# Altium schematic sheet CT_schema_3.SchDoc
size 372 x 328 mm
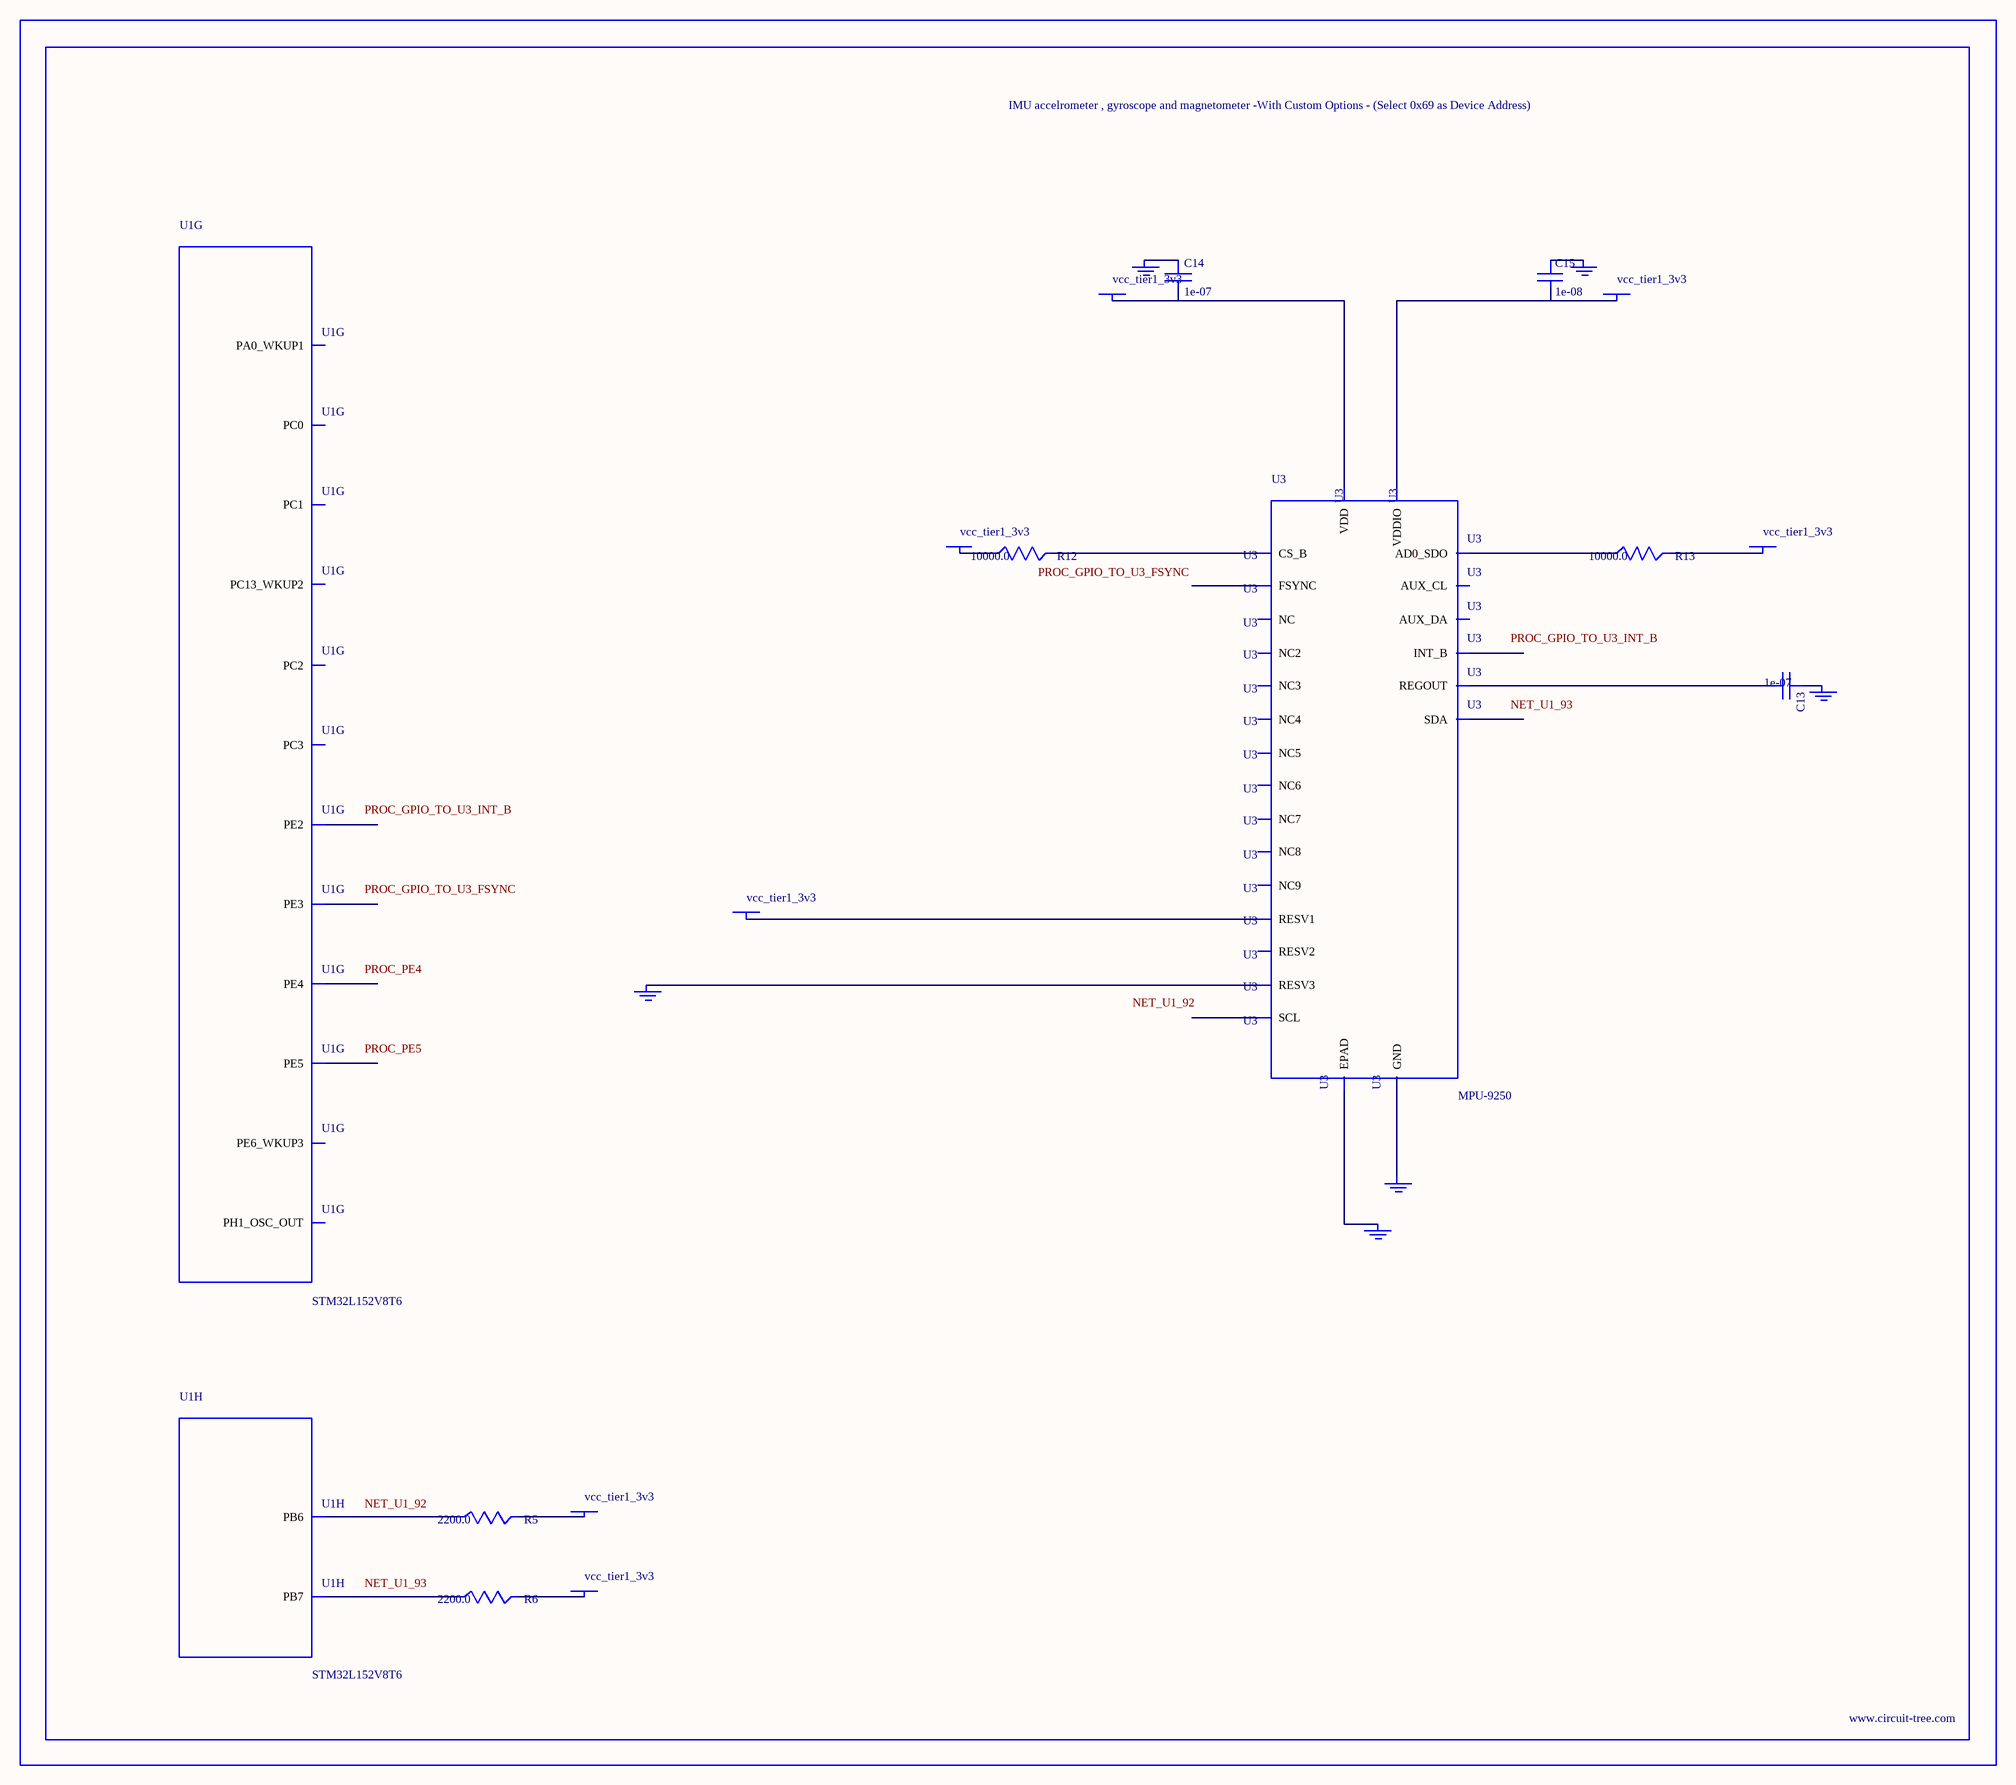
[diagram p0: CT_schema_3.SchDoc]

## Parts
BORDER2  (no value)
C13  1e-07  [C0402]
C14  1e-07  [C0402]
C15  1e-08  [C0402]
GND_INSTANCE_2_0  (no value)
GND_INSTANCE_2_1  (no value)
GND_INSTANCE_2_2  (no value)
GND_INSTANCE_2_3  (no value)
GND_INSTANCE_2_4  (no value)
GND_INSTANCE_2_5  (no value)
POWER_INSTANCE_2_0  vcc_tier1_3v3
POWER_INSTANCE_2_1  vcc_tier1_3v3
POWER_INSTANCE_2_2  vcc_tier1_3v3
POWER_INSTANCE_2_3  vcc_tier1_3v3
POWER_INSTANCE_2_4  vcc_tier1_3v3
POWER_INSTANCE_2_5  vcc_tier1_3v3
POWER_INSTANCE_2_6  vcc_tier1_3v3
R5  2200.0  [R0603]
R6  2200.0  [R0603]
R12  10000.0  [R0603]
R13  10000.0  [R0603]
U1  STM32L152V8T6  [LQFP100]  (parts G,H of 8)
U3  MPU-9250  [QFN24_2]

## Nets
NetC13_1: C13.1 GND_INSTANCE_2_1.0(GND)
NetC13_2: C13.2 U3.10(REGOUT)
NetC14_1: C14.1 GND_INSTANCE_2_2.0(GND)
NetC14_2: C14.2 POWER_INSTANCE_2_3.0(PWR) U3.13(VDD)
NetC15_1: C15.1 GND_INSTANCE_2_0.0(GND)
NetC15_2: C15.2 POWER_INSTANCE_2_1.0(PWR) U3.8(VDDIO)
NetGND_INSTANCE_2_3_0: GND_INSTANCE_2_3.0(GND) U3.20(RESV3)
NetGND_INSTANCE_2_4_0: GND_INSTANCE_2_4.0(GND) U3.25(EPAD)
NetGND_INSTANCE_2_5_0: GND_INSTANCE_2_5.0(GND) U3.18(GND)
NetPOWER_INSTANCE_2_0_0: POWER_INSTANCE_2_0.0(PWR) U3.1(RESV1)
NetPOWER_INSTANCE_2_2_0: POWER_INSTANCE_2_2.0(PWR) R13.2
NetPOWER_INSTANCE_2_4_0: POWER_INSTANCE_2_4.0(PWR) R12.1
NetPOWER_INSTANCE_2_5_0: POWER_INSTANCE_2_5.0(PWR) R5.2
NetPOWER_INSTANCE_2_6_0: POWER_INSTANCE_2_6.0(PWR) R6.2
NetR5_1: R5.1 U1.92(PB6)
NetR6_1: R6.1 U1.93(PB7)
NetR12_2: R12.2 U3.22(CS_B)
NetR13_1: R13.1 U3.9(AD0_SDO)

Not connected (* = marked no-connect by the designer): U1 1(PE2) 2(PE3) 3(PE4) 4(PE5) 5(PE6_WKUP3) 7(PC13_WKUP2) 13(PH1_OSC_OUT) 15(PC0) 16(PC1) 17(PC2) 18(PC3) 23(PA0_WKUP1); U3 2(NC) 3(NC2) 4(NC3) 5(NC4) 6(NC5) 7(AUX_CL) 11(FSYNC) 12(INT_B) 14(NC6) 15(NC7) 16(NC8) 17(NC9) 19(RESV2) 21(AUX_DA) 23(SCL) 24(SDA)

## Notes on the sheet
- Labels drawn without touching a wire or pin: NET_U1_92, NET_U1_93, PROC_GPIO_TO_U3_FSYNC, PROC_GPIO_TO_U3_INT_B, PROC_PE4, PROC_PE5

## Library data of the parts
BORDER2 = BORDER_PAGE2
C13 C14 = C0402C104K3RACTU
C15 = C0402C103K3RAC
GND_INSTANCE_2_0-GND_INSTANCE_2_5 = GND
POWER_INSTANCE_2_0-POWER_INSTANCE_2_6 = PWR
R5 R6 = RC0603JR-072K2L
R12 R13 = RC0603JR-0710KL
